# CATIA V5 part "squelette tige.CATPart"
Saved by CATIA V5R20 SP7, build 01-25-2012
Part number: squelette tige vérin gauche
Bounding box of the stored display mesh (mm): x -17.69 to 11.46, y -54 to 23, z 45.721 to 47.6
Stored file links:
  F:\Travaux\Modélisations\CFAO_2011\CFAO_2011_MMS\CFAO_2011_MMS_DONE\CFAO_2011_MMS_jboiteux\Catia\squelette tige.CATPart
  U:\finthinkmotion\stepper.CATProduct
  F:\Travaux\Modélisations\CFAO_2011\CFAO_2011_MMS\CFAO_2011_MMS_DONE\CFAO_2011_MMS_jboiteux\Catia\part4.CATPart
  F:\Travaux\Modélisations\CFAO_2011\CFAO_2011_MMS\CFAO_2011_MMS_DONE\CFAO_2011_MMS_jboiteux\Catia\Part1.CATPart
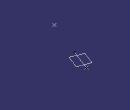
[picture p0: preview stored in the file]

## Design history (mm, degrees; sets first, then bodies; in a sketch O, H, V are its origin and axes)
Set1
  Line1: linked copy from another document
  Line2: linked copy from another document
Body1 (main body)
  Point1: type OnCurve, Support Line1, Ratio 0
  Point2: type OnCurve, Support Line2, Ratio 0
  Line3: type PtPt, FirstPoint Point1, SecondPoint Point2
  Line4: type PtDir, RefPoint Point1, Direction Line3, Start 0, End 30
  Plane1: type 2Lines, Element1 Line4, Element2 Line1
